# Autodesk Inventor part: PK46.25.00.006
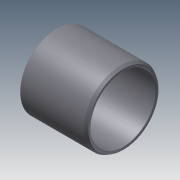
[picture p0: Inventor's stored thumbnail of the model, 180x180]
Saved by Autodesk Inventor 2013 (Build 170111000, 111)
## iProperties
Created: 2005-05
Part Number: PK46.25.00.006
Material: Steel, Mild
Document SubType Name: Modeling
Designer: PVitaliy
Manufacturer: Standard
Standards Organization: Custom
Density: 7.86 g/cm^3
Author: PVitaliy
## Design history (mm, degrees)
sketch "Эскиз2"
  geometry: L1 (0, 0)-(45.09, 0); L2 (0, 45)-(78.536, 45); L3 (0, 45)-(0, 40); L4 (0, 40)-(82, 40); L5 (82, 40)-(82, 43); L6 (78.536, 45)-(82, 43)
  constraints: 12 end point, 3 horizontal, 2 vertical, 1 point on line, 1 other
  dimensions: "d0" = 90 diameter of L2 L1; "d1" = 80 diameter of L4 L1; "d3" = 82 distance of L3.end L4.end; "d4" = 30 deg angle of L6 L2; "d5" = 86 diameter of L5.end L1
revolve "Вращение1" sketch "Эскиз2" stored, may be unused: angle "d6" = 90 deg
chamfer "Фаска1" distance "d7" = 0.5; stored, may be unused: second distance "d8" = 2, angle "d9" = 45 deg
body "Solid1"
